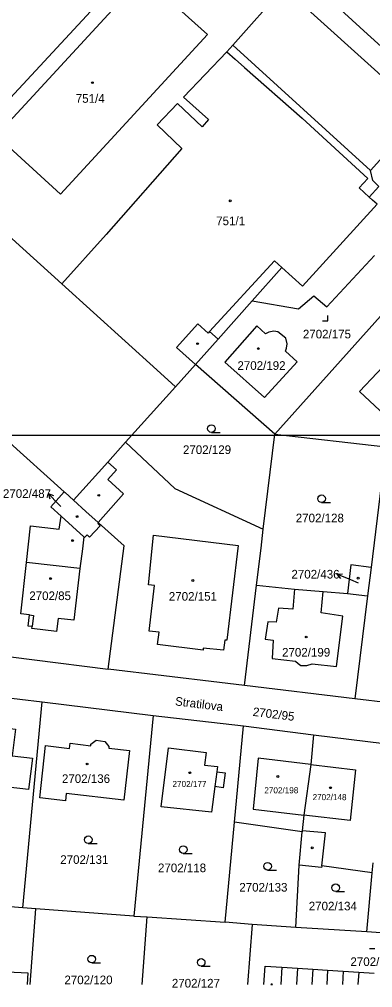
# Model space of a CAD drawing. Extents: x -496682 to -495776, y -1088797 to -1088018.
# Drawn here: x -496399.5 to -496329.9, y -1088570.1 to -1088379.3 of the extents above; entities that cross this region are included whole.
import ezdxf

# ---------------------------------------------------------------- set-up
doc = ezdxf.new("R2010")
doc.units = 0
for name, color, linetype in [('Hranice parcel', 7, 'Continuous'), ('Parcelní čísla', 7, 'Continuous'), ('Pop  PČ popisy', 7, 'Continuous'), ('Vnitřní kresba', 7, 'Continuous'), ('Vrstva 63', 7, 'Continuous'), ('Značky budov', 7, 'Continuous'), ('Značky kultur', 7, 'Continuous')]:
    doc.layers.add(name, color=color, linetype=linetype)

msp = doc.modelspace()

# ---------------------------------------------------------------- linework, layer by layer
at = {"layer": 'Hranice parcel'}
for p, q in [((-496415.13, -1088409.73), (-496376.05, -1088367.51)), ((-496322.98, -1088431.74), (-496349.17, -1088461.01)), ((-496368.72, -1088451.67), (-496364.78, -1088447.29)), ((-496349.17, -1088461.01), (-496364.78, -1088447.29)), ((-496378.57, -1088462.59), (-496368.72, -1088451.67)), ((-496351.43, -1088479.75), (-496349.17, -1088461.01)), ((-496349.17, -1088461.01), (-496327.31, -1088463.52)), ((-496390.64, -1088472.36), (-496401.99, -1088462.09)), ((-496327.31, -1088463.52), (-496330.22, -1088487.27)), ((-496386.81, -1088481.22), (-496391.24, -1088477.18)), ((-496330.22, -1088487.27), (-496330.91, -1088492.86)), ((-496355.16, -1088510.55), (-496352.76, -1088490.73)), ((-496334.86, -1088492.38), (-496330.91, -1088492.86)), ((-496330.91, -1088492.86), (-496333.4, -1088513.15)), ((-496333.4, -1088513.15), (-496355.16, -1088510.55)), ((-496413.5, -1088511.53), (-496394.97, -1088513.78)), ((-496398.8, -1088554.34), (-496394.97, -1088513.78)), ((-496394.97, -1088513.78), (-496373.13, -1088516.44)), ((-496373.13, -1088516.44), (-496376.91, -1088555.96)), ((-496373.13, -1088516.44), (-496355.34, -1088518.51)), ((-496357.11, -1088537.48), (-496355.34, -1088518.51)), ((-496355.34, -1088518.51), (-496341.52, -1088520.23)), ((-496341.52, -1088520.23), (-496327.65, -1088521.96)), ((-496358.95, -1088557.14), (-496357.11, -1088537.48)), ((-496343.76, -1088539.36), (-496357.11, -1088537.48)), ((-496344.37, -1088545.92), (-496343.76, -1088539.36)), ((-496345.03, -1088558.23), (-496344.37, -1088545.92)), ((-496330.02, -1088547.42), (-496329.78, -1088545.45)), ((-496331.02, -1088559.09), (-496330.02, -1088547.42)), ((-496398.8, -1088554.34), (-496417.53, -1088552.98)), ((-496396.26, -1088554.52), (-496398.8, -1088554.34)), ((-496397.38, -1088569.45), (-496396.26, -1088554.52)), ((-496376.91, -1088555.96), (-496396.26, -1088554.52)), ((-496376.91, -1088555.96), (-496374.34, -1088556.11)), ((-496375.31, -1088569.45), (-496374.34, -1088556.11)), ((-496374.34, -1088556.11), (-496358.95, -1088557.14)), ((-496353.66, -1088557.62), (-496358.95, -1088557.14)), ((-496353.66, -1088557.62), (-496354.53, -1088569.45)), ((-496345.03, -1088558.23), (-496353.66, -1088557.62)), ((-496331.02, -1088559.09), (-496345.03, -1088558.23)), ((-496304.43, -1088561.01), (-496331.02, -1088559.09)), ((-496347.76, -1088566.06), (-496347.98, -1088569.45)), ((-496347.76, -1088566.06), (-496344.71, -1088566.26)), ((-496344.71, -1088566.26), (-496344.92, -1088569.45)), ((-496344.71, -1088566.26), (-496341.67, -1088566.46)), ((-496341.67, -1088566.46), (-496341.87, -1088569.45)), ((-496341.67, -1088566.46), (-496338.77, -1088566.65)), ((-496338.77, -1088566.65), (-496338.95, -1088569.45)), ((-496338.77, -1088566.65), (-496335.68, -1088566.85)), ((-496335.68, -1088566.85), (-496335.85, -1088569.45)), ((-496335.68, -1088566.85), (-496332.64, -1088567.05)), ((-496332.64, -1088567.05), (-496332.8, -1088569.45)), ((-496332.64, -1088567.05), (-496329.59, -1088567.25))]:
    msp.add_line(p, q, dxfattribs=at)
for points in [[(-496248.09, -1088462.93), (-496246.94, -1088461.48), (-496246.55, -1088459.79), (-496247.27, -1088457.92), (-496249.13, -1088456.06), (-496330.94, -1088382.16), (-496352.76, -1088362.17), (-496394.53, -1088322.76)], [(-496347.42, -1088372.97), (-496357.46, -1088384.36), (-496358.63, -1088385.68), (-496367.13, -1088394.6), (-496362.2, -1088399), (-496363.47, -1088400.45), (-496368.31, -1088395.83), (-496372.35, -1088400.06), (-496367.51, -1088404.68)], [(-496320.05, -1088397.68), (-496324.85, -1088393.33), (-496347.42, -1088372.97)], [(-496353.62, -1088434.72), (-496347.79, -1088428.16), (-496343.74, -1088431.85), (-496329.03, -1088415.71), (-496329.94, -1088414.89), (-496330.57, -1088414.27), (-496328.66, -1088412.18), (-496329.87, -1088411.04), (-496330.29, -1088409.02), (-496320.05, -1088397.68)], [(-496367.51, -1088404.68), (-496382.38, -1088421.63), (-496391.09, -1088431.4)], [(-496415.13, -1088409.73), (-496412.88, -1088411.76), (-496391.09, -1088431.4)], [(-496353.62, -1088434.72), (-496344.49, -1088436.33), (-496341.48, -1088433.73), (-496338.95, -1088435.92), (-496329.51, -1088425.77)], [(-496391.09, -1088431.4), (-496372.42, -1088448.31), (-496368.72, -1088451.67)], [(-496364.78, -1088447.29), (-496360.33, -1088442.29), (-496353.62, -1088434.72)], [(-496350.98, -1088441.21), (-496352.73, -1088439.67), (-496359.04, -1088446.84), (-496351.17, -1088453.77), (-496344.79, -1088446.72), (-496347.09, -1088444.64), (-496346.85, -1088444.04), (-496346.74, -1088443.18), (-496346.99, -1088442.1), (-496348.56, -1088440.87), (-496349.36, -1088440.72), (-496350.32, -1088440.88), (-496350.98, -1088441.21)], [(-496388.84, -1088473.99), (-496382.08, -1088466.49), (-496378.57, -1088462.59)], [(-496378.57, -1088462.59), (-496368.85, -1088471.68), (-496351.43, -1088479.75)], [(-496391.24, -1088477.18), (-496393.28, -1088475.32), (-496390.64, -1088472.36)], [(-496390.64, -1088472.36), (-496390.47, -1088472.51), (-496388.84, -1088473.99)], [(-496388.84, -1088473.99), (-496386.37, -1088476.23), (-496383.99, -1088478.38), (-496383.91, -1088478.46)], [(-496386.81, -1088481.22), (-496387.08, -1088483.58), (-496387.6, -1088487.48), (-496388.73, -1088497.67), (-496391.86, -1088497.32), (-496392.17, -1088499.92), (-496397, -1088499.33), (-496396.95, -1088498.93), (-496397.74, -1088498.83), (-496397.47, -1088496.62), (-496399.19, -1088496.41), (-496398.08, -1088486.32), (-496397.28, -1088479.07), (-496391.65, -1088479.71), (-496391.24, -1088477.18)], [(-496383.91, -1088478.46), (-496384.05, -1088478.58), (-496383.6, -1088479.07), (-496385.69, -1088481.28), (-496386.15, -1088480.86), (-496386.65, -1088481.37), (-496386.81, -1088481.22)], [(-496381.96, -1088507.33), (-496378.87, -1088483.01), (-496383.91, -1088478.46)], [(-496352.76, -1088490.73), (-496351.88, -1088483.47), (-496351.43, -1088479.75)], [(-496330.22, -1088487.27), (-496334.22, -1088486.77), (-496334.86, -1088492.38)], [(-496352.76, -1088490.73), (-496345.27, -1088491.55), (-496339.65, -1088492), (-496334.86, -1088492.38)], [(-496282.64, -1088498.73), (-496287, -1088503.42), (-496289.92, -1088506.42), (-496292.31, -1088508.31), (-496294.86, -1088509.98), (-496297.59, -1088511.42), (-496300.41, -1088512.61), (-496303.13, -1088513.62), (-496305.98, -1088514.4), (-496309.41, -1088514.94), (-496310.93, -1088514.97), (-496313.55, -1088515.26), (-496317.24, -1088515.06), (-496320.12, -1088514.76), (-496333.4, -1088513.15)], [(-496427.43, -1088500.69), (-496425.57, -1088501.8), (-496381.96, -1088507.33)], [(-496355.16, -1088510.55), (-496360.04, -1088509.96), (-496381.96, -1088507.33)], [(-496401.7, -1088530.59), (-496411.17, -1088529.49), (-496410.56, -1088524.24), (-496411.46, -1088524.14), (-496410.89, -1088519.24), (-496410.59, -1088519.28), (-496410.48, -1088518.4), (-496408.38, -1088518.63), (-496408.48, -1088519.52), (-496405.68, -1088519.85), (-496405.48, -1088518.47), (-496400.24, -1088519.14), (-496400.91, -1088524.37), (-496396.87, -1088524.88), (-496397.69, -1088531.06), (-496401.7, -1088530.59)], [(-496385.39, -1088522.41), (-496385.39, -1088522.11), (-496384.36, -1088521.3), (-496382.62, -1088521.57), (-496381.87, -1088522.55), (-496381.89, -1088522.88), (-496377.78, -1088523.37), (-496378.93, -1088533.14), (-496390.24, -1088531.8), (-496390.41, -1088533.27), (-496395.43, -1088532.68), (-496394.32, -1088522.39), (-496389.59, -1088522.97), (-496389.46, -1088521.92), (-496385.39, -1088522.41)], [(-496341.52, -1088520.23), (-496342.09, -1088526.09), (-496343.43, -1088536.06), (-496343.75, -1088539.19), (-496343.76, -1088539.36)], [(-496360.97, -1088530.45), (-496361.62, -1088535.52), (-496371.55, -1088534.42), (-496370.09, -1088522.81), (-496362.68, -1088523.75), (-496362.99, -1088526.22), (-496360.46, -1088526.49), (-496360.59, -1088527.55), (-496358.97, -1088527.77), (-496359.36, -1088530.67), (-496360.97, -1088530.45)], [(-496330.02, -1088547.42), (-496339.93, -1088546.06), (-496339.96, -1088546.41), (-496344.37, -1088545.92)], [(-496351.35, -1088569.45), (-496351.07, -1088565.84), (-496347.76, -1088566.06)], [(-496404.72, -1088569.45), (-496404.57, -1088566.8), (-496397.81, -1088567.16), (-496397.94, -1088569.45)]]:
    msp.add_lwpolyline(points, dxfattribs=at)
at = {"layer": 'Pop  PČ popisy'}
for p, q in [((-496391.7, -1088474.87), (-496393.79, -1088472.71)), ((-496393.79, -1088472.71), (-496392.73, -1088473.08)), ((-496393.79, -1088472.71), (-496393.45, -1088473.78)), ((-496391.3, -1088475.28), (-496391.7, -1088474.87)), ((-496336.95, -1088488.62), (-496335.84, -1088488.53)), ((-496334.17, -1088489.74), (-496336.95, -1088488.62)), ((-496336.95, -1088488.62), (-496336.21, -1088489.46)), ((-496332.71, -1088490.34), (-496334.17, -1088489.74))]:
    msp.add_line(p, q, dxfattribs=at)
at = {"layer": 'Vnitřní kresba'}
for p, q in [((-496404.03, -1088402.17), (-496375.12, -1088370.85)), ((-496375.12, -1088370.85), (-496362.41, -1088382.27)), ((-496362.41, -1088382.27), (-496391.38, -1088413.68)), ((-496357.46, -1088384.36), (-496330.29, -1088409.02)), ((-496358.63, -1088385.68), (-496356.99, -1088387.12)), ((-496356.99, -1088387.12), (-496355.14, -1088388.75)), ((-496355.14, -1088388.75), (-496343.81, -1088398.74)), ((-496391.38, -1088413.68), (-496404.03, -1088402.17)), ((-496362, -1088440.78), (-496349.22, -1088426.85)), ((-496349.22, -1088426.85), (-496347.79, -1088428.16)), ((-496332.48, -1088452.62), (-496313.58, -1088432.42)), ((-496362, -1088440.78), (-496360.33, -1088442.29)), ((-496321.03, -1088463.34), (-496332.48, -1088452.62)), ((-496382.08, -1088466.49), (-496380.33, -1088468.06)), ((-496380.33, -1088468.06), (-496382.05, -1088469.97)), ((-496382.05, -1088469.97), (-496378.96, -1088472.76)), ((-496378.96, -1088472.76), (-496383.99, -1088478.38)), ((-496374.06, -1088490.72), (-496373.04, -1088480.91)), ((-496373.04, -1088480.91), (-496356.38, -1088482.92)), ((-496356.38, -1088482.92), (-496358.63, -1088501.62)), ((-496387.6, -1088487.48), (-496398.08, -1088486.32)), ((-496372.88, -1088490.84), (-496374.06, -1088490.72)), ((-496373.92, -1088499.81), (-496372.88, -1088490.84)), ((-496345.27, -1088491.55), (-496345.62, -1088495.5)), ((-496340.03, -1088496.23), (-496339.65, -1088492)), ((-496348.47, -1088495.29), (-496348.93, -1088498.04)), ((-496345.62, -1088495.5), (-496348.47, -1088495.29)), ((-496397.47, -1088496.62), (-496396.68, -1088496.72)), ((-496396.68, -1088496.72), (-496396.95, -1088498.93)), ((-496335.76, -1088496.85), (-496340.03, -1088496.23)), ((-496337, -1088506.77), (-496335.76, -1088496.85)), ((-496350.54, -1088497.97), (-496351.08, -1088501.39)), ((-496348.93, -1088498.04), (-496350.54, -1088497.97)), ((-496371.94, -1088500.04), (-496373.92, -1088499.81)), ((-496372.25, -1088502.48), (-496371.94, -1088500.04)), ((-496363.31, -1088503.59), (-496372.25, -1088502.48)), ((-496359.03, -1088501.57), (-496359.27, -1088503.58)), ((-496358.63, -1088501.62), (-496359.03, -1088501.57)), ((-496351.08, -1088501.39), (-496349.52, -1088501.63)), ((-496349.52, -1088501.63), (-496349.69, -1088505.23)), ((-496363.26, -1088503.19), (-496363.31, -1088503.59)), ((-496359.27, -1088503.58), (-496363.26, -1088503.19)), ((-496349.69, -1088505.23), (-496345.09, -1088505.75)), ((-496345.09, -1088505.75), (-496344.59, -1088506.18)), ((-496344.59, -1088506.18), (-496344.03, -1088506.6)), ((-496344.03, -1088506.6), (-496342.84, -1088506.62)), ((-496342.84, -1088506.62), (-496341.84, -1088506.25)), ((-496341.84, -1088506.25), (-496337, -1088506.77)), ((-496352.43, -1088524.87), (-496353.41, -1088534.88)), ((-496342.09, -1088526.09), (-496352.43, -1088524.87)), ((-496360.59, -1088527.55), (-496360.97, -1088530.45)), ((-496342.09, -1088526.09), (-496333.25, -1088527.13)), ((-496333.25, -1088527.13), (-496334.32, -1088537.15)), ((-496353.41, -1088534.88), (-496343.43, -1088536.06)), ((-496334.32, -1088537.15), (-496343.43, -1088536.06)), ((-496339.2, -1088539.59), (-496343.75, -1088539.19)), ((-496339.93, -1088546.06), (-496339.2, -1088539.59))]:
    msp.add_line(p, q, dxfattribs=at)
for points in [[(-496330.57, -1088414.27), (-496332.53, -1088412.43), (-496330.87, -1088410.6), (-496343.81, -1088398.74)], [(-496362, -1088440.78), (-496362.27, -1088441.08), (-496364.31, -1088439.25), (-496368.51, -1088443.94), (-496364.78, -1088447.29)]]:
    msp.add_lwpolyline(points, dxfattribs=at)
at = {"layer": 'Vrstva 63'}
msp.add_lwpolyline([(-496137.35, -1088164.24), (-496137.35, -1088461.24), (-496557.35, -1088461.24), (-496557.35, -1088164.24)], close=True, dxfattribs=at)
at = {"layer": 'Značky budov'}
msp.add_line((-496349.93, -1088569.45), (-496349.63, -1088569.45), dxfattribs=at)
for centre in [(-496385.1, -1088391.74), (-496357.95, -1088415.03), (-496364.38, -1088443.17), (-496352.42, -1088444.14), (-496383.85, -1088473.06), (-496388.12, -1088477.24), (-496389, -1088481.97), (-496393.33, -1088489.47), (-496365.31, -1088489.84), (-496332.75, -1088489.38), (-496342.97, -1088500.98), (-496386.15, -1088526), (-496365.9, -1088527.72), (-496348.58, -1088528.46), (-496338.19, -1088530.68), (-496341.79, -1088542.52)]:
    msp.add_circle(centre, 0.175, dxfattribs=at)
msp.add_arc((-496349.78, -1088569.54), 0.175, 31.2705, 148.7295, dxfattribs=at)
at = {"layer": 'Značky kultur'}
for p, q in [((-496338.75, -1088438.65), (-496338.75, -1088437.65)), ((-496339.75, -1088438.65), (-496338.75, -1088438.65)), ((-496361.65, -1088460.66), (-496359.9, -1088460.66)), ((-496339.96, -1088474.49), (-496338.21, -1088474.49)), ((-496385.92, -1088541.67), (-496384.17, -1088541.67)), ((-496367.2, -1088543.63), (-496365.45, -1088543.63)), ((-496350.6, -1088546.9), (-496348.85, -1088546.9)), ((-496337.18, -1088551.15), (-496335.43, -1088551.15)), ((-496330.49, -1088562.33), (-496329.49, -1088562.33)), ((-496385.22, -1088565.21), (-496383.47, -1088565.21)), ((-496363.67, -1088565.86), (-496361.92, -1088565.86))]:
    msp.add_line(p, q, dxfattribs=at)
for centre in [(-496361.65, -1088459.91), (-496339.96, -1088473.74), (-496385.92, -1088540.92), (-496367.2, -1088542.88), (-496350.6, -1088546.15), (-496337.18, -1088550.4), (-496385.22, -1088564.46), (-496363.67, -1088565.11)]:
    msp.add_circle(centre, 0.75, dxfattribs=at)

# ---------------------------------------------------------------- texts
at = {"layer": 'Parcelní čísla'}
for s, height, p in [('751/4', 1.7, (-496388.37, -1088395.7)), ('751/1', 1.7, (-496360.71, -1088419.82)), ('2702/175', 1.7, (-496343.64, -1088442.13)), ('2702/192', 1.7, (-496356.53, -1088448.33)), ('2702/129', 1.7, (-496367.26, -1088464.91)), ('2702/487', 1.7, (-496402.72, -1088473.56)), ('2702/128', 1.7, (-496345.04, -1088478.37)), ('2702/436', 1.7, (-496345.89, -1088489.45)), ('2702/85', 1.7, (-496397.53, -1088493.7)), ('2702/151', 1.7, (-496370.04, -1088493.82)), ('2702/199', 1.7, (-496347.74, -1088504.84)), ('2702/136', 1.7, (-496391.1, -1088529.74)), ('2702/177', 1.2, (-496369.32, -1088530.54)), ('2702/198', 1.2, (-496351.23, -1088531.78)), ('2702/148', 1.2, (-496341.73, -1088533.13)), ('2702/131', 1.7, (-496391.43, -1088545.69)), ('2702/118', 1.7, (-496372.18, -1088547.32)), ('2702/133', 1.7, (-496356.16, -1088551.15)), ('2702/134', 1.7, (-496342.48, -1088554.85)), ('2702/126', 1.7, (-496334.27, -1088565.81)), ('2702/120', 1.7, (-496390.61, -1088569.4)), ('2702/127', 1.7, (-496369.45, -1088570.05))]:
    msp.add_text(s, height=height, dxfattribs=at).set_placement(p)
msp.add_text('2702/95', height=1.7, rotation=353, dxfattribs=at).set_placement((-496353.57, -1088516.51))
at = {"layer": 'Pop  PČ popisy'}
msp.add_text('Stratilova', height=1.7, rotation=353, dxfattribs=at).set_placement((-496368.88, -1088514.43))

doc.saveas('drawing.dxf')
